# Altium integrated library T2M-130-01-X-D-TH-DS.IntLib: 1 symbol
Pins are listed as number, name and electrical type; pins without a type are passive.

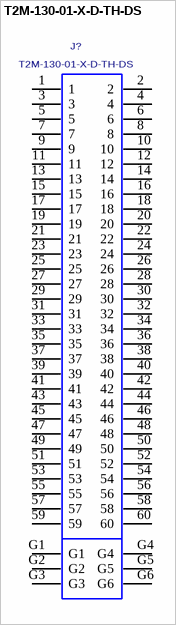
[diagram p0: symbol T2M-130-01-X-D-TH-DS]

## T2M-130-01-X-D-TH-DS
designator J?
2mm Shrouded TerminaL Strip, Thru-Hole, 60 Pins, Dual Screw Down.; MANUFACTURER: SAMTEC
footprint T2M-130-01-X-D-TH-DS
pins: 1, 2, 3, 4, 5, 6, 7, 8, 9, 10, 11, 12, 13, 14, 15, 16, 17, 18, 19, 20, 21, 22, 23, 24, 25, 26, 27, 28, 29, 30, 31, 32, 33, 34, 35, 36, 37, 38, 39, 40, 41, 42, 43, 44, 45, 46, 47, 48, 49, 50, 51, 52, 53, 54, 55, 56, 57, 58, 59, 60, G1, G2, G3, G4, G5, G6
